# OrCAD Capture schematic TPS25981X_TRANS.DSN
size E; title: TPS25981x 2.7 V–16 V, 10-A, 6-mO eFuse with Transient; rev: 1.0; note: Datasheet: SLVSGG6    EVM: SLVUCE5; note: Current Monitor and Transient Overcurrent Blanking
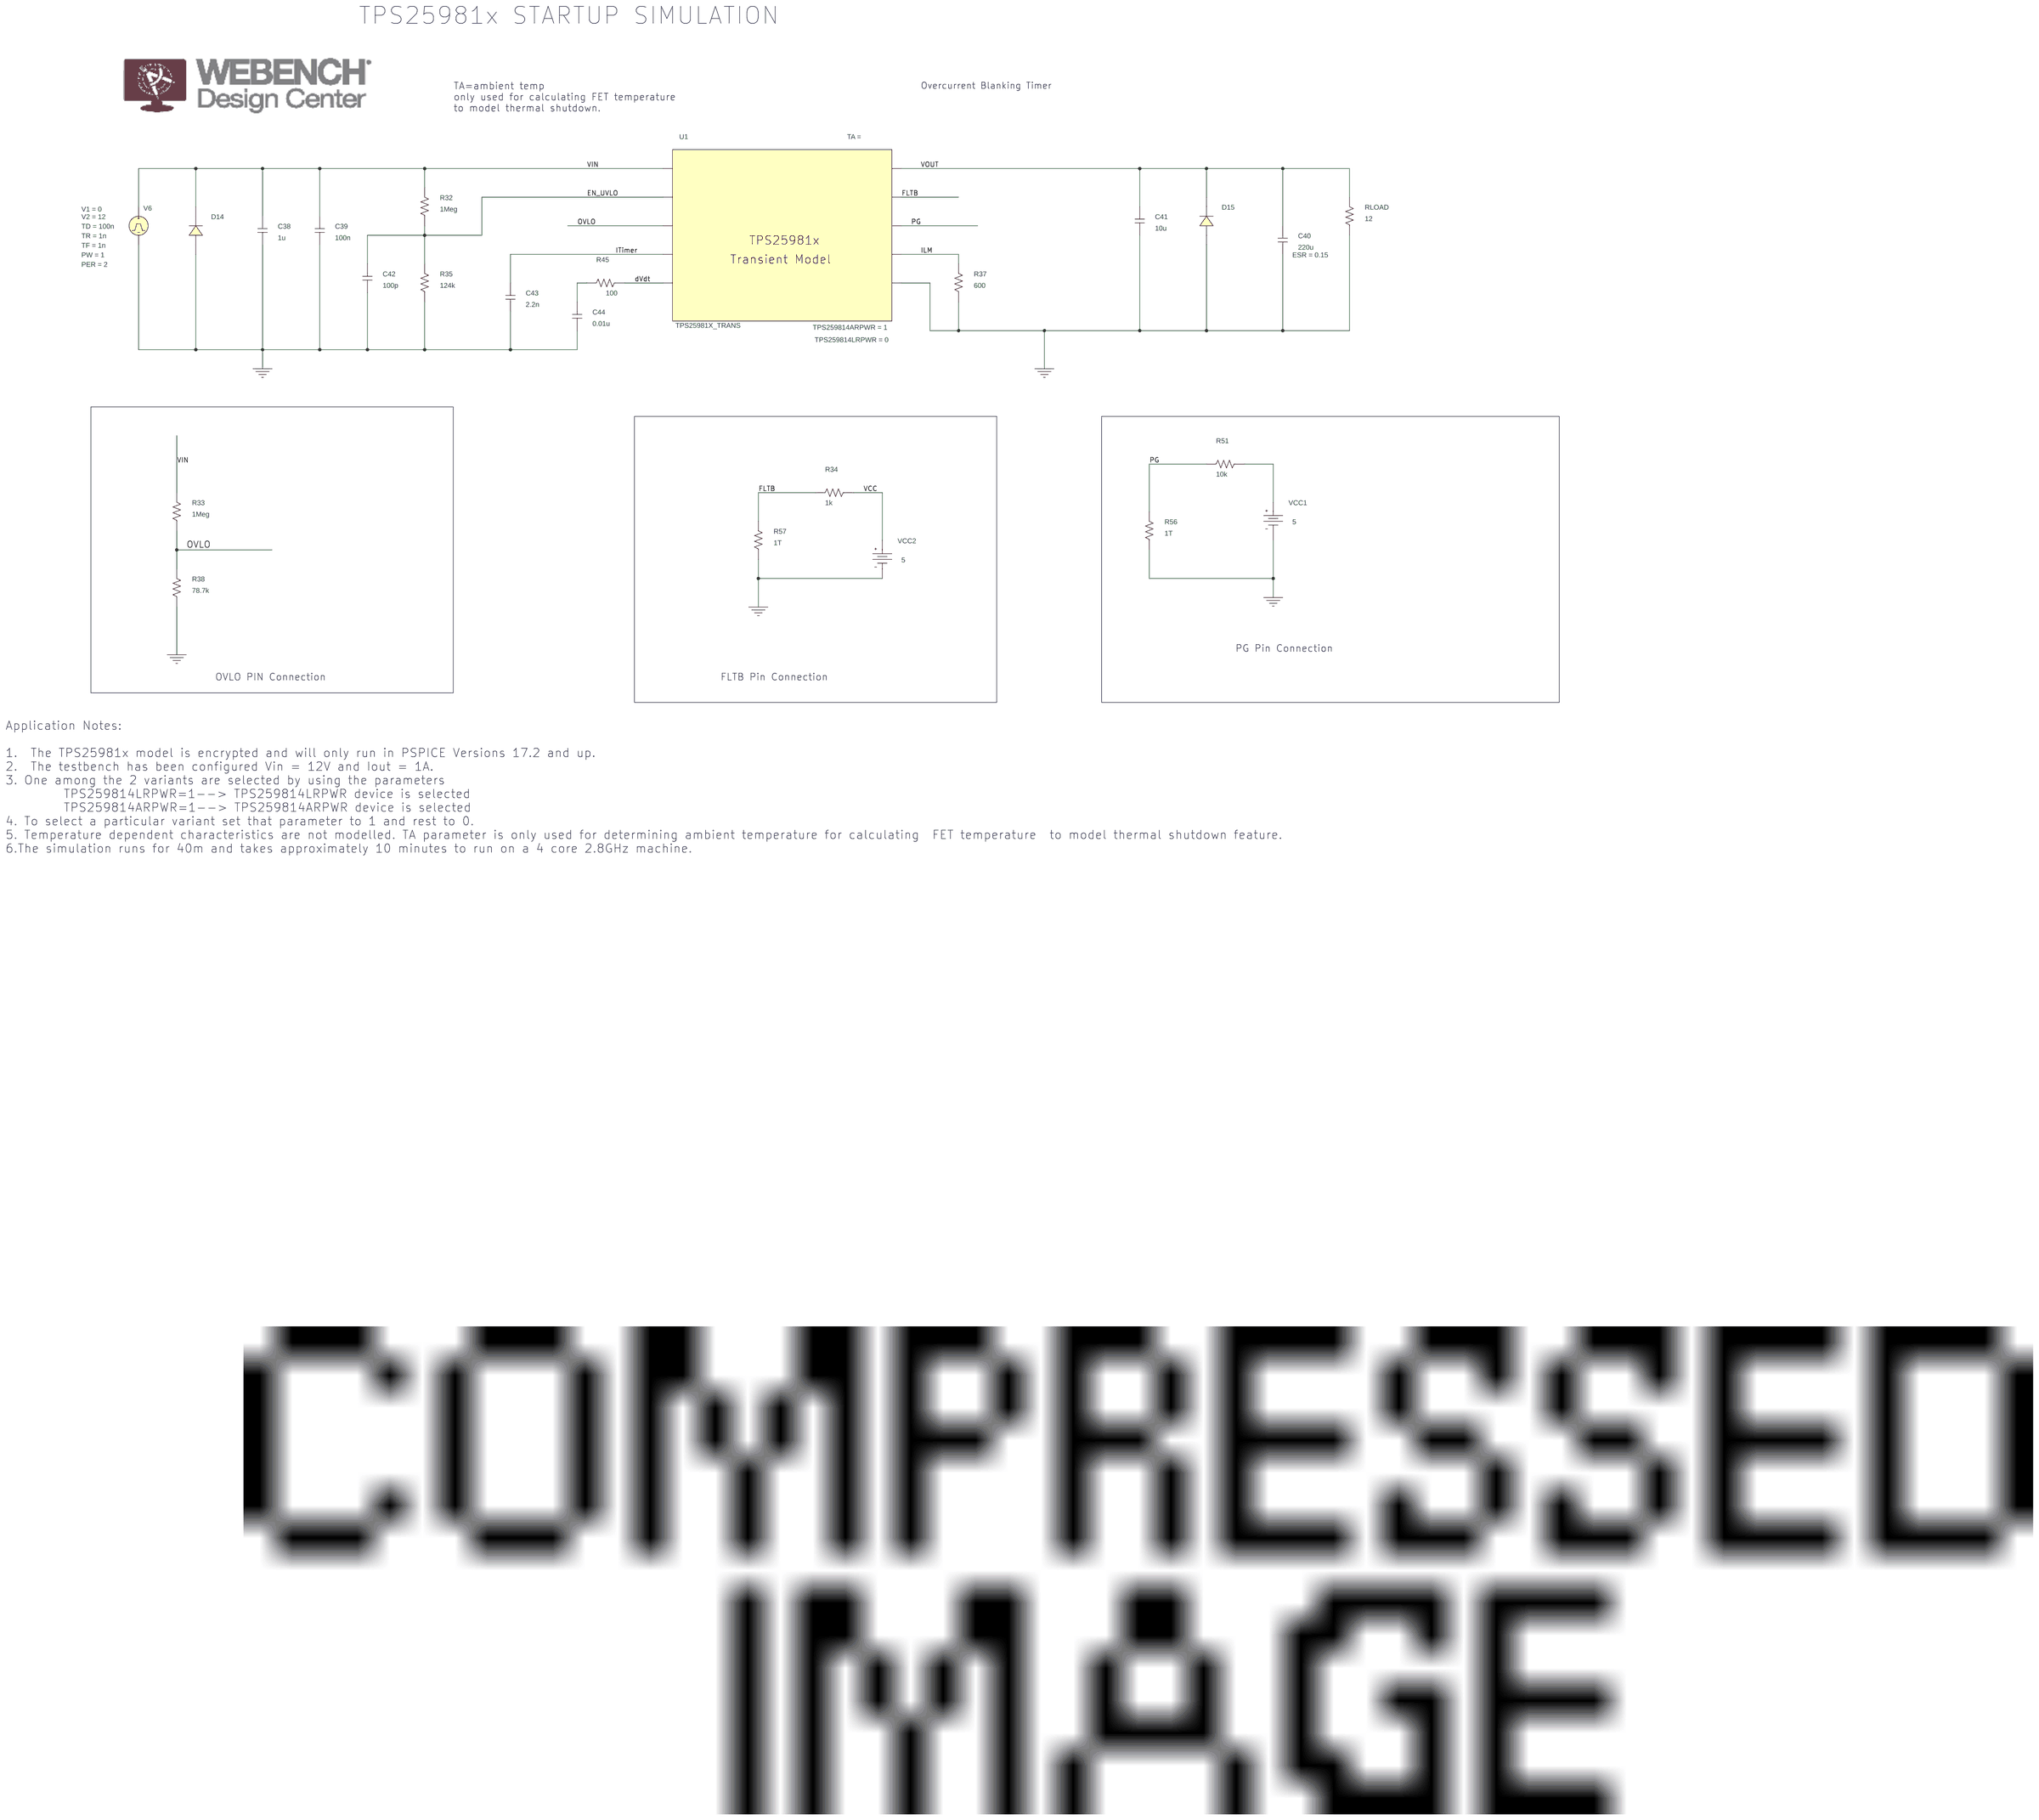
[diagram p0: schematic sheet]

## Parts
C38  1u  [RAD/CK05]
C39  100n  [RAD/CK05]
C40  220u  [RAD/CK05]
C41  10u  [RAD/CK05]
C42  100p  [RAD/CK05]
C43  2.2n  [RAD/CK05]
C44  0.01u  [RAD/CK05]
D14  SMBJ18A
D15  B330A
R32  1Meg  [AX/RC05]
R33  1Meg  [AX/RC05]
R34  1k  [AX/RC05]
R35  124k  [AX/RC05]
R37  600  [AX/RC05]
R38  78.7k  [AX/RC05]
R45  100  [AX/RC05]
R51  10k  [AX/RC05]
R56  1T  [AX/RC05]
R57  1T  [AX/RC05]
RLOAD  12  [AX/RC05]
U1  TPS25981X_TRANS
V6  VPULSE
VCC1  VDC
VCC2  VDC

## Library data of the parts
C38 C39 C41-C44 = C
C40 = C: AppProp: InductiveSlave:;SRF:;PrevCap:220u;PrevESL:; ESR: 0.15
D14 = D_D1: PSpiceTemplate: X^@REFDES  %C %A @MODEL
D15 = D_D1: PSpiceTemplate: D^@REFDES  %A %C @MODEL ?AREA/@AREA/
R32-R35 R37 R38 R45 R51 R56 R57 RLOAD = R
U1 = TPS25981X_TRANS: TPS259814ARPWR: 1; TPS259814LRPWR: 0
V6 = VPULSE: PER: 2; PW: 1; TD: 100n; TF: 1n; TR: 1n; V1: 0; V2: 12
VCC1 VCC2 = VDC: DC: 5

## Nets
VCC: R34.1 VCC2.0(+)
VIN: C38.2 C39.2 D14.1(C) R32.2 R33.2 U1.IN V6.1(+)
0: C38.1 C39.1 C40.1 C41.1 C42.1 C43.1 C44.1 D14.2(A) D15.2(A) R35.1 R37.1 R38.1 R56.1 R57.1 RLOAD.1 U1.GND V6.2(-) VCC1.1(-) VCC2.1(-)
dVdt: R45.1 U1.DVDT
EN_UVLO: C42.2 R32.1 R35.2 U1.EN_UVLO
FLTB: R34.2 R57.2 U1.FLTB
ILM: R37.2 U1.ILM
ITimer: C43.2 U1.ITIMER
OVLO: R33.1 R38.2 U1.OVLO
PG: R51.2 R56.2 U1.PG
VOUT: C40.2 C41.2 D15.1(C) RLOAD.2 U1.OUT
N16780012: C44.2 R45.2
N16780128: R51.1 VCC1.0(+)

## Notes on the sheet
- TPS25981x STARTUP SIMULATION
- TA=ambient temp
  only used for calculating FET temperature
  to model thermal shutdown.
- Overcurrent Blanking Timer
- PG Pin Connection
- OVLO PIN Connection
- FLTB Pin Connection
- Application Notes:
  1.  The TPS25981x model is encrypted and will only run in PSPICE Versions 17.2 and up.
  2.  The testbench has been configured Vin = 12V and Iout = 1A.
  3. One among the 2 variants are selected by using the parameters
           TPS259814LRPWR=1--> TPS259814LRPWR device is selected
           TPS259814ARPWR=1--> TPS259814ARPWR device is selected
  4. To select a particular variant set that parameter to 1 and rest to 0.
  5. Temperature dependent characteristics are not modelled. TA parameter is only used for determining ambient temperature for calculating  FET temperature  to model thermal shutdown feature.
  6.The simulation runs for 40m and takes approximately 10 minutes to run on a 4 core 2.8GHz machine.
